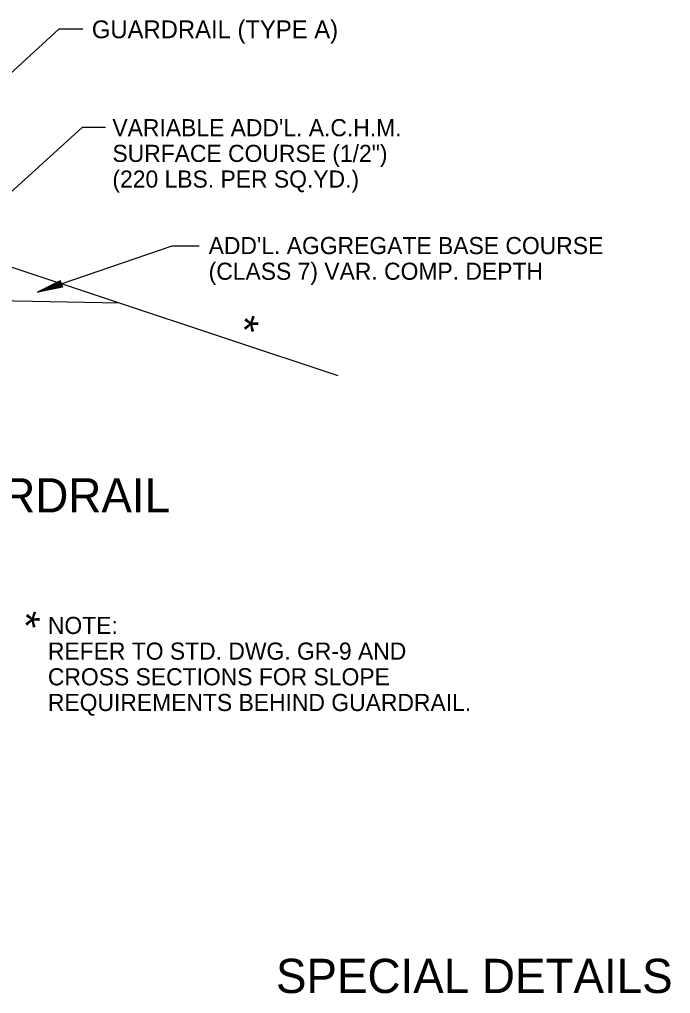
# Model space of a CAD drawing. Extents: x -2842 to 2681, y -2139 to 474.
# Drawn here: x 605.6 to 833.9, y -1711.6 to -1370.2 of the extents above; entities that cross this region are included whole.
import ezdxf

# ---------------------------------------------------------------- set-up
doc = ezdxf.new("R2010")
doc.units = 0
for name, color, linetype in [('BDR_Plan Profile Grid 3', 7, 'Continuous'), ('R_Border', 7, 'Continuous'), ('R_Border Notes', 7, 'Continuous'), ('SHT_NPLT', 7, 'Continuous')]:
    doc.layers.add(name, color=color, linetype=linetype)

msp = doc.modelspace()

# ---------------------------------------------------------------- linework, layer by layer
at = {"layer": 'BDR_Plan Profile Grid 3'}
msp.add_line((356.1, -1463.82), (640.63, -1469.52), dxfattribs=at)
at = {"layer": 'R_Border Notes'}
for p, q in [((619.88, -1461.8), (611.91, -1465.75)), ((611.91, -1465.75), (620.25, -1462.88)), ((620.62, -1463.96), (611.91, -1465.75)), ((620.17, -1462.67), (613.53, -1464.95)), ((620.33, -1463.09), (613.67, -1465.38)), ((620.11, -1462.45), (615.09, -1464.18)), ((620.41, -1463.31), (615.39, -1465.03)), ((620.02, -1462.23), (616.7, -1463.38)), ((620.48, -1463.53), (617.15, -1464.68)), ((619.95, -1462.01), (618.31, -1462.58)), ((620.55, -1463.75), (618.91, -1464.31)), ((619.88, -1461.8), (620.62, -1463.96))]:
    msp.add_line(p, q, dxfattribs=at)
for points in [[(627.78, -1373.58), (619.32, -1373.58), (560.38, -1427.61)], [(635.72, -1408.01), (627.52, -1408.01), (575.86, -1454.74)], [(668.54, -1449.59), (659.01, -1449.59), (611.91, -1465.75)]]:
    msp.add_lwpolyline(points, dxfattribs=at)
at = {"layer": 'SHT_NPLT'}
msp.add_line((599.03, -1455.66), (717.26, -1494.98), dxfattribs=at)

# ---------------------------------------------------------------- texts
at = {"layer": 'R_Border'}
for s, height, p in [('GUARDRAIL (TYPE A) ', 6.25, (630.94, -1376.76)), ("VARIABLE ADD'L. A.C.H.M. ", 6, (638.16, -1411.11)), ('SURFACE COURSE (1/2")', 6, (638.16, -1420.11)), ('(220 LBS. PER SQ.YD.) ', 6, (638.16, -1429.11)), ("ADD'L. AGGREGATE BASE COURSE ", 6, (671.91, -1452.42)), ('(CLASS 7) VAR. COMP. DEPTH ', 6, (671.91, -1461.42)), (' WIDENING FOR GUARDRAIL ', 12, (435.51, -1542.97)), ('NOTE:', 6, (615.53, -1585.56)), ('REFER TO STD. DWG. GR-9 AND ', 6, (615.53, -1594.56)), ('CROSS SECTIONS FOR SLOPE ', 6, (615.53, -1603.56)), ('REQUIREMENTS BEHIND GUARDRAIL.', 6, (615.53, -1612.56)), ('SPECIAL DETAILS', 12, (695.51, -1711.4))]:
    msp.add_text(s, height=height, dxfattribs=at).set_placement(p)
for p in [(681.6, -1483.43), (604.95, -1587.09)]:
    msp.add_text('*', height=10.7, rotation=341.5651, dxfattribs=at).set_placement(p)

doc.saveas('drawing.dxf')
